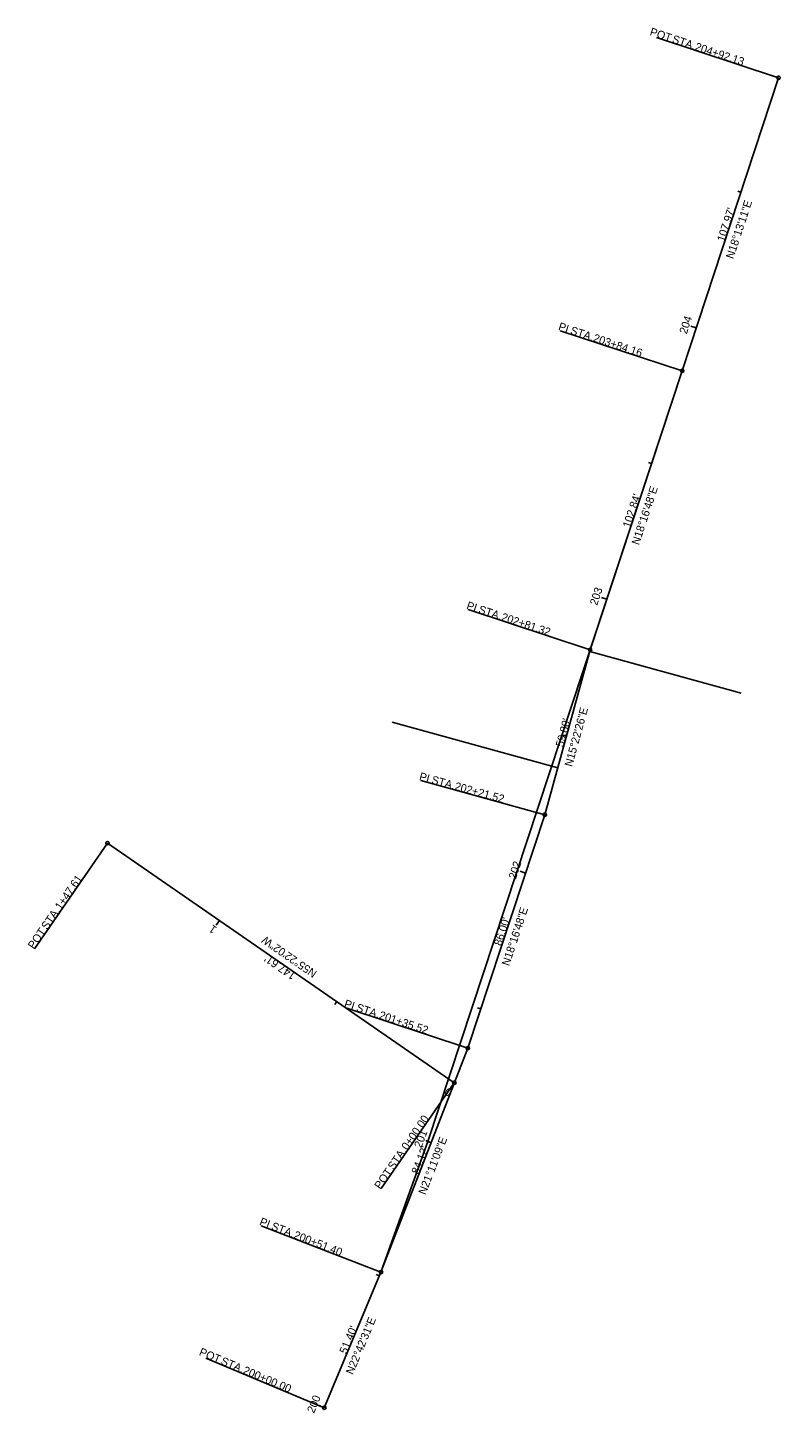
# Model space of a CAD drawing. Extents: x 139619 to 139883, y 537439 to 537924.
import ezdxf

# ---------------------------------------------------------------- set-up
doc = ezdxf.new("R2010")
doc.units = 0
for name, color, linetype in [('GE_P_Alignment', 7, 'Continuous'), ('GE_P_Alignment_100_Bearings', 7, 'Continuous'), ('GE_P_Alignment_100_Cardinal_Points', 7, 'Continuous'), ('GE_P_Alignment_100_Distances', 7, 'Continuous'), ('GE_P_Alignment_100_Stations', 7, 'Continuous'), ('GE_P_Driveway_CL', 7, 'Continuous'), ('SC_Scratch1', 7, 'Continuous')]:
    doc.layers.add(name, color=color, linetype=linetype)

msp = doc.modelspace()

# ---------------------------------------------------------------- linework, layer by layer
at = {"layer": 'GE_P_Alignment'}
for p, q in [((139848.58, 537803.68), (139882.34, 537906.24)), ((139816.33, 537706.03), (139848.58, 537803.68)), ((139800.47, 537648.37), (139816.33, 537706.03)), ((139773.5, 537566.71), (139800.47, 537648.37)), ((139768.78, 537554.54), (139647.32, 537638.43)), ((139743.1, 537488.28), (139773.5, 537566.71)), ((139723.25, 537440.86), (139743.1, 537488.28)), ((139723.25, 537440.86), (139743.1, 537488.28))]:
    msp.add_line(p, q, dxfattribs=at)
at = {"layer": 'GE_P_Alignment_100_Cardinal_Points'}
for p, q in [((139882.34, 537906.24), (139839.6, 537920.31)), ((139848.58, 537803.68), (139805.84, 537817.75)), ((139816.33, 537706.03), (139773.6, 537720.15)), ((139800.47, 537648.37), (139757.08, 537660.3)), ((139647.32, 537638.43), (139621.75, 537601.41)), ((139773.5, 537566.71), (139730.77, 537580.83)), ((139768.78, 537554.54), (139743.21, 537517.52)), ((139743.1, 537488.28), (139701.14, 537504.54)), ((139723.25, 537440.86), (139681.74, 537458.23))]:
    msp.add_line(p, q, dxfattribs=at)
for centre in [(139882.34, 537906.24), (139848.58, 537803.68), (139816.33, 537706.03), (139800.47, 537648.37), (139647.32, 537638.43), (139773.5, 537566.71), (139768.78, 537554.54), (139743.1, 537488.28), (139723.25, 537440.86)]:
    msp.add_circle(centre, 0.6, dxfattribs=at)
at = {"layer": 'GE_P_Alignment_100_Stations'}
for p, q in [((139869.17, 537866.22), (139868.03, 537866.59)), ((139853.53, 537818.72), (139851.63, 537819.35)), ((139837.87, 537771.24), (139836.73, 537771.62)), ((139822.18, 537723.77), (139820.28, 537724.39)), ((139808.02, 537675.83), (139806.86, 537676.15)), ((139793.72, 537627.93), (139791.82, 537628.56)), ((139686.5, 537611.38), (139685.36, 537609.73)), ((139727.64, 537582.96), (139726.96, 537581.97)), ((139778.04, 537580.46), (139776.9, 537580.83)), ((139768.78, 537554.54), (139767.64, 537552.9)), ((139760.66, 537533.59), (139758.79, 537534.31)), ((139742.55, 537486.98), (139741.45, 537487.45)), ((139723.25, 537440.86), (139721.41, 537441.63))]:
    msp.add_line(p, q, dxfattribs=at)
at = {"layer": 'GE_P_Driveway_CL'}
for p, q in [((139816.18, 537705.5), (139869.27, 537690.9)), ((139804.98, 537664.78), (139746.98, 537680.73))]:
    msp.add_line(p, q, dxfattribs=at)
at = {"layer": 'SC_Scratch1'}
for p, q in [((139759.51, 537534.02), (139848.58, 537803.68)), ((139743.1, 537488.28), (139759.51, 537534.02)), ((139723.25, 537440.86), (139743.1, 537488.28))]:
    msp.add_line(p, q, dxfattribs=at)

# ---------------------------------------------------------------- texts
at = {"layer": 'GE_P_Alignment_100_Bearings'}
for s, rotation, p in [('N18°13\'11"E', 71.7802, (139866.47, 537842.67)), ('N18°16\'48"E', 71.7201, (139833.45, 537742.56)), ('N15°22\'26"E', 74.6261, (139810.01, 537664.97)), ('N18°16\'48"E', 71.7201, (139787.98, 537595.25)), ('N55°22\'02"W', 145.3672, (139720.91, 537593.44)), ('N21°11\'09"E', 68.8141, (139758.67, 537515.16)), ('N22°42\'31"E', 67.2915, (139733.22, 537452.23))]:
    msp.add_text(s, height=2.8, rotation=rotation, dxfattribs=at).set_placement(p)
at = {"layer": 'GE_P_Alignment_100_Cardinal_Points'}
for s, rotation, p in [('POT', 341.7802, (139837.02, 537921.2)), (' STA. ', 341.7802, (139843.86, 537918.95)), ('204+92.13', 341.7802, (139852.84, 537916)), ('PI', 341.7802, (139804.99, 537818.07)), (' STA. ', 341.7802, (139808.21, 537817.01)), ('203+84.16', 341.7802, (139817.19, 537814.06)), ('PI', 341.7201, (139772.82, 537720.45)), (' STA. ', 341.7201, (139776.04, 537719.38)), ('202+81.32', 341.7201, (139785.02, 537716.42)), ('PI', 344.6261, (139756.29, 537660.56)), (' STA. ', 344.6261, (139759.57, 537659.66)), ('202+21.52', 344.6261, (139768.68, 537657.16)), ('1+47.61', 55.3672, (139630.97, 537614.83)), (' STA. ', 55.3672, (139625.6, 537607.05)), ('POT', 55.3672, (139621.51, 537601.13)), ('PI', 341.7201, (139729.99, 537581.12)), (' STA. ', 341.7201, (139733.22, 537580.06)), ('201+35.52', 341.7201, (139742.19, 537577.1)), ('0+00.00', 55.3672, (139752.32, 537530.78)), (' STA. ', 55.3672, (139746.94, 537523)), ('POT', 55.3672, (139742.85, 537517.08)), ('PI', 338.8141, (139700.32, 537504.9)), (' STA. ', 338.8141, (139703.48, 537503.68)), ('200+51.40', 338.8141, (139712.29, 537500.26)), ('POT', 337.2915, (139679.17, 537459.35)), (' STA. ', 337.2915, (139685.82, 537456.57)), ('200+00.00', 337.2915, (139694.54, 537452.92))]:
    msp.add_text(s, height=2.8, rotation=rotation, dxfattribs=at).set_placement(p)
at = {"layer": 'GE_P_Alignment_100_Distances'}
for s, rotation, p in [("107.97'", 71.7802, (139863.33, 537848.63)), ("102.84'", 71.7201, (139830.32, 537748.53)), ("59.80'", 74.6261, (139806.88, 537671.85)), ("86.00'", 71.7201, (139785.2, 537602.27)), ("147.61'", 145.3672, (139713.52, 537592.66)), ("84.12'", 68.8141, (139756.25, 537522.32)), ("51.40'", 67.2915, (139730.99, 537459.45))]:
    msp.add_text(s, height=2.8, rotation=rotation, dxfattribs=at).set_placement(p)
at = {"layer": 'GE_P_Alignment_100_Stations'}
for s, rotation, p in [('204', 71.7802, (139850.14, 537816.4)), ('203', 71.7201, (139818.78, 537721.44)), ('202', 71.7201, (139790.32, 537625.6)), ('1', 145.3672, (139685.83, 537608.8)), ('0', 145.3672, (139768.27, 537551.86)), ('201', 68.8141, (139757.19, 537531.55)), ('200', 67.2915, (139719.65, 537438.74))]:
    msp.add_text(s, height=2.8, rotation=rotation, dxfattribs=at).set_placement(p)

doc.saveas('drawing.dxf')
